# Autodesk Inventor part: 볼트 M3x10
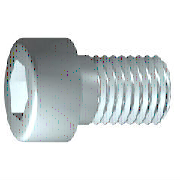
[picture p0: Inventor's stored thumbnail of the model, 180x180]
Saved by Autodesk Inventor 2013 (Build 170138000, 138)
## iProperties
Created: 2012-02
Part Number: 볼트 M3x10
Material: 스테인리스강
Description: 6각 소켓 머리 캡 나사
Document SubType Name: Modeling
Standard: ISO 4762
Designer: mduedu
Standard Revision: Fourth edition 2004-03-01
Standards Organization: ISO
Language: ko-KR
Size Designation: M3 x 10
Categories: <MemberInstance><Categories><Category DisplayName="조임쇠" InternalName="e4da775c-781d-43d5-af7c-5136215cf5a6" Mnemonic="FSTN"><Category DisplayName="볼트" InternalN
Density: 7.75 g/cm^3
Mass: 1.02639 g
Surface Area: 2.01851 cm^2
Volume: 0.132438 cm^3
IsCustomPart: 0
Author: mduedu
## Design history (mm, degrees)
sketch "스케치1"
  geometry: L1 (-0.867, 0)-(10, 0); L2 (10, 0)-(10, 1.5); L3 (10, 1.5)-(1.25, 1.5); L4 (1.25, 1.5)-(0.943, 1.5); L5 (0.943, 1.5)-(0, 1.5); L6 (0, 1.5)-(0, 2.75); L7 (0, 2.75)-(-3, 2.75); L8 (-3, 2.75)-(-3, 1.443); L9 (-3, 1.443)-(-1.7, 1.443); L10 (-1.7, 1.443)-(-0.867, 0); L11 (-5.6, 0)-(12.6, 0) reference; L12 (0, -0.55)-(0, 3.3) reference; L13 (1.25, 1.5)-(0, 1.5)
  constraints: 22 end point, 6 parallel, 2 collinear, 2 perpendicular, 1 horizontal, 1 point on line
  dimensions: "d1" = 8.75 distance from line of L3.end L2 (= GEL); "d2" = 0.30683 distance of L4.end L3.end (computed from GAL); "d3" = 3 distance between parallel lines of L8 L6 (= KOH); "d4" = 1.3 distance of L8.end L9.end (= INTI); "d5" = 60 deg angle of L10 L1; "d6" = 3 diameter of L3 L1 (= GD); "d7" = 3 diameter of L5 L1 (= BDM); "d8" = 2.88675 diameter of L9 L1 (= 1.1547 x SW); "d9" = 5.5 diameter of L7 L1 (= KOD); "d26" = 10 distance between parallel lines of L12 L2 (= NLG)
revolve "본체" sketch "스케치1" stored, may be unused: angle "d10" = 90 deg
sketch "스케치2"
  geometry: L1 (0, -3.85)-(0, 3.85) reference; L2 (-3.85, 0)-(3.85, 0) reference; L3 (1.443, 0)-(0.722, -1.25); L4 (0.722, -1.25)-(-0.722, -1.25); L5 (-0.722, -1.25)-(-1.443, 0); L6 (-1.443, 0)-(-0.722, 1.25); L7 (-0.722, 1.25)-(0.722, 1.25); L8 (0.722, 1.25)-(1.443, 0); 2 further points
  constraints: 12 end point, 1 coincident, 1 horizontal alignment, 1 point on line, 12 other
extrude "슬롯" join sketch "스케치2" stored distance "d11" = 10; taper "d12" = 0 deg
workplane "Work Plane1"
fillet "Fillet2" dims "d30" = 0.1 (= R)
body "Solid1"
fillet "모깎기1" dims "d17" = 0.3 (= RR)
feature "스레드" dims "d13" = 8.75 (= GEL), "d14" = 0
chamfer "모따기1" distance "d15" = 0.30673 (= -0.5 x SPD + 0.5 x GD); stored, may be unused: second distance "d16" = 0.30673 (= GUL), angle "d27" = 45 deg
other parameters: "GD" = 3 [user parameter; used in 2 equation terms], "NLG" = 10 [user parameter; used in 1 equation term], "GEL" = 8.75 [user parameter; used in 2 equation terms], "KOD" = 5.5 [user parameter; used in 1 equation term], "KOH" = 3 [user parameter; used in 1 equation term], "INTI" = 1.3 [user parameter; used in 1 equation term], "GAL" = 0.30673 (= 0.61345 x PTC) [user parameter; used in 1 equation term], "GUL" = 0.30673 (= 0.61345 x PTC) [user parameter; used in 1 equation term], "BDM" = 3 (= NND) [user parameter; used in 1 equation term], "SW" = 2.5 [user parameter; used in 2 equation terms], "RR" = 0.3 [user parameter; used in 1 equation term], "SPD" = 2.38655 (= NND - 1.2269 x PTC) [user parameter; used in 1 equation term], "d19" = 0, "d28" = 0, "d29" = 0, "R" = 0.1 [user parameter; used in 1 equation term], "TOA" = 30 deg [user parameter], "GD1" = 2.38655 (= THREADDIA - 1.2269 x PTC) [user parameter], "THREADDIA" = 3 [user parameter; used in 1 equation term], "FAWI" = 45 deg [user parameter], "PTC" = 0.5 [user parameter; used in 5 equation terms], "NND" = 3 [user parameter; used in 2 equation terms], "E0" = 2.8875 (= 1.155 x SW) [user parameter]
